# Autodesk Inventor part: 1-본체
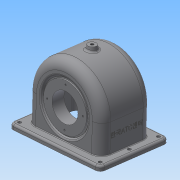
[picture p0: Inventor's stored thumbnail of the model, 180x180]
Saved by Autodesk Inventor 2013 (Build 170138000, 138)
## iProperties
Created: 2015-09
Part Number: 1-본체
Material: 일반
Document SubType Name: Modeling
Designer: ST
Density: 1 g/cm^3
Author: ST
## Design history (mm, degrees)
sketch "스케치1"
  geometry: L1 (-57, 47)-(-57, 0); L2 (57, 47)-(57, 0); L3 (-57, 0)-(57, 0); A1 r 57 centre (0, 47) between (57, 47) and (-57, 47); 3 further points
  constraints: 6 end point, 2 coincident, 2 point on circle, 2 tangent, 1 centre point, 1 midpoint, 1 parallel, 1 perpendicular, 1 vertical, 1 vertical alignment
  dimensions: "d23" = 114 diameter of A1; "d28" = 47 distance of A1.centre point (0, 0)
extrude "돌출5" new body sketch "스케치1" distance "d29" = 77; taper "d30" = 0 deg
feature "쉘2" dims "d31" = 5
sketch "스케치6"
  geometry: L1 (109, 5)-(5, 5) reference; L2 (5, 5)-(5, 72) reference; L3 (5, 72)-(109, 72) reference; L4 (109, 72)-(109, 5) reference; L5 (114, 0)-(0, 0) reference; L6 (0, 0)-(0, 77) reference; L7 (127, -13.5)-(127, 90.5); L8 (127, 90.5)-(-13, 90.5); L9 (-13, 90.5)-(-13, -13.5); L10 (-13, -13.5)-(127, -13.5); 5 further points
  constraints: 8 end point, 4 midpoint, 2 horizontal, 2 vertical, 1 horizontal alignment, 1 vertical alignment
  dimensions: "d32" = 104 distance of L8.end L9.end; "d34" = 140 distance of L7.end L8.end
extrude "돌출6" join sketch "스케치6" distance "d35" = 7; taper "d36" = 0 deg
sketch "스케치7"
  geometry: C1 r 31 at (0, 47); A1 r 57 centre (0, 47) between (57, 47) and (-57, 47) reference; 1 further point
  constraints: 1 centre point, 1 coincident
  dimensions: "d37" = 62 diameter of C1
extrude "돌출7" join sketch "스케치7" distance "d39" = 10; taper "d40" = 0 deg
node "작업 평면1"
sketch "스케치12"
  geometry: L1 (70, 90.5)-(-70, 90.5) reference; L2 (-31, -10)-(31, -10) reference; C1 r 6 at (0, 37); 1 further point
  constraints: 1 centre point, 1 vertical alignment
  dimensions: "d71" = 12 diameter of C1; "d94" = 47 distance from line of L2 C1.centre
extrude "돌출10" join sketch "스케치12" stored distance "d72" = 13; taper "d73" = 10 deg
sketch "스케치13"
  geometry: C1 r 6 at (0, 0) reference; 2 further points
  constraints: 1 coincident
hole "구멍1" sketch "스케치13" at (0, 0) diameter "d74" = 4.459; stored, may be unused: countersink angle "d78" = 90 deg, drill point angle "d80" = 118 deg; dims "d75" = 6, "d76" = 4, "d77" = 2, "d79" = 8
sketch "스케치14"
  geometry: L1 (127, 13.5)-(-13, 13.5) reference; L2 (-13, 13.5)-(-13, -90.5) reference; C1 r 2.5 at (-5, -82.5); C2 r 2.5 at (-5, -38.5); C3 r 2.5 at (-5, 5.5); C4 r 2.5 at (119, 5.5); C5 r 2.5 at (119, -38.5); C6 r 2.5 at (119, -82.5); 1 further point
  constraints: 6 centre point, 5 equal radius, 4 vertical alignment, 3 horizontal alignment
  dimensions: "d81" = 44 distance of C2.centre C3.centre; "d83" = 44 distance of C1.centre C2.centre; "d84" = 8 distance from line of C3.centre L1; "d85" = 124 distance of C4.centre C3.centre; "d86" = 8 distance from line of C3.centre L2; "d87" = 5 diameter of C1
extrude "돌출11" cut sketch "스케치14" stored distance "d88" = 13; taper "d89" = 0 deg
fillet "모깎기2" dims "d90" = 7
fillet "모깎기3" dims "d91" = 3
fillet "모깎기4" dims "d92" = 14
sketch "스케치15"
  geometry: C1 r 31 at (0, 0) reference; C2 r 20 at (0, 0); 1 further point
  constraints: 1 centre point, 1 coincident
  dimensions: "d95" = 40 diameter of C2
extrude "돌출12" cut sketch "스케치15" stored distance "d97" = 13; taper "d98" = 0 deg
sketch "스케치16"
  geometry: C1 r 20 at (0, 0) reference; C2 r 31 at (0, 0) reference; A1 r 24 centre (0, 0) between (0, 24) and (0, -24); 3 further points
  constraints: 4 point on circle, 2 horizontal alignment, 2 vertical alignment, 1 centre point, 1 coincident
  dimensions: "d99" = 48 diameter of A1
hole "구멍2" sketch "스케치16" at (0, 24), (0, -24), (-24, 0), (24, 0) diameter "d101" = 2.459; stored, may be unused: countersink angle "d105" = 90 deg, drill point angle "d107" = 118 deg; dims "d102" = 6, "d103" = 4, "d104" = 2, "d106" = 8
sketch "스케치20"
  geometry: L1 (-63, 40)-(-63, 0) reference; L2 (-69.5, -7)-(-76.5, -7) reference; 2 further points
  constraints: 1 other
  dimensions: "d123" = 38.5 distance from line of point (-24.5, 23) L1; "d124" = 30 distance from line of point (-24.5, 23) L2
feature "엠보싱1" sketch "스케치20" dims "d23" = 114, "d28" = 47, "d125" = 0.5, "d126" = 0
fillet "모깎기5" dims "d127" = 1
fillet "모깎기6" dims "d128" = 9
fillet "모깎기7" dims "d142" = 3
sketch "스케치25"
  geometry: L1 (47, 91.743)-(47, -40.519); L2 (75, 58)-(47, 58); L3 (47, 72)-(47, 63) reference; L4 (47, 63)-(47, 63) reference; L5 (47, 72)-(47, 63) reference; L6 (47, 72)-(47, 72) reference; L7 (47, 72)-(47, 58); L8 (47, 72)-(86.747, 72); L9 (86.747, 72)-(75, 58); 1 further point
  constraints: 10 end point, 2 perpendicular, 1 point on line, 1 vertical
  dimensions: "d157" = 47 distance from line of point (0, 0) L1; "d158" = 56 diameter of L2.start L1; "d170" = 50 deg angle of L2 L9; "d171" = 14 vertical distance of L8.end L2.start
revolve "회전4" sketch "스케치25" stored, may be unused: angle "d161" = 90 deg
sketch "스케치28"
  geometry: L1 (84.416, 77)-(81.899, 74); L2 (47, 77)-(47, -10); L3 (47, 77)-(90, 77) reference; L4 (67, -10)-(27, -10) reference; L5 (86.747, 72)-(75, 58) reference; L6 (81.899, 74)-(47, 74); L7 (84.416, 77)-(47, 77); L8 (47, 77)-(47, 74); 1 further point
  constraints: 10 end point, 3 point on line, 1 collinear, 1 midpoint, 1 perpendicular, 1 vertical
  dimensions: "d172" = 47 horizontal distance of point (0, 0) L2.end; "d175" = 5 distance between parallel lines of L1 L5; "d176" = 3 distance between parallel lines of L3 L6
revolve "회전6" sketch "스케치28" stored, may be unused: angle "d177" = 90 deg
sketch "스케치29"
  geometry: C1 r 34.899 at (0, 0) reference; C2 r 33 at (0, 0); 1 further point
  constraints: 1 centre point, 1 coincident
  dimensions: "d178" = 66 diameter of C2
extrude "돌출18" join sketch "스케치29" distance "d180" = 2; taper "d181" = 0 deg
sketch "스케치30"
  geometry: C1 r 33 at (0, 0) reference; C2 r 20 at (0, 0); 1 further point
  constraints: 1 centre point, 1 coincident
  dimensions: "d182" = 40 diameter of C2
extrude "돌출19" cut sketch "스케치30" stored distance "d184" = 3; taper "d185" = 0 deg
fillet "모깎기9" dims "d186" = 0.5
fillet "모깎기10" dims "d187" = 3
sketch "스케치31"
  geometry: C1 r 20 at (0, 0) reference; C2 r 33 at (0, 0) reference; A1 r 27.5 centre (0, 0) between (0, 27.5) and (0, -27.5); 3 further points
  constraints: 4 point on circle, 2 horizontal alignment, 2 vertical alignment, 1 centre point, 1 coincident
  dimensions: "d188" = 55 diameter of A1
hole "구멍4" sketch "스케치31" at (0, 27.5), (0, -27.5), (27.5, 0), (-27.5, 0) diameter "d190" = 2.459; stored, may be unused: countersink angle "d194" = 90 deg, drill point angle "d196" = 118 deg; dims "d191" = 7, "d192" = 4, "d193" = 2, "d195" = 9
node "솔리드2"
node "투영된 루프2"
